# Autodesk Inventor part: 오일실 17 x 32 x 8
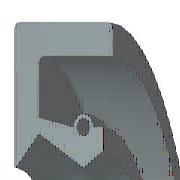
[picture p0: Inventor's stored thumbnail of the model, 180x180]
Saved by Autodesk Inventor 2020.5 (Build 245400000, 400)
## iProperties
Created: 2012-02
Part Number: 오일실 17 x 32 x 8
Material: 고무
Description: 오일-실
Document SubType Name: Modeling
Standard: KS B 2804
Designer: mduedu
Standards Organization: KS
Language: ko-KR
Size Designation: D - 17 32 8
Categories: <MemberInstance><Categories><Category DisplayName="샤프트 부품" InternalName="7f7aeb1f-a693-4053-b835-cee3144e0d98" Mnemonic="SHFT"><Category DisplayName="실링" Intern
Density: 0.93 g/cm^3
Appearance: 고무 - 검은색 - 버전 1.1
IsCustomPart: 1
Author: mduedu
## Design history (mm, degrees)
revolve "본체" stored, may be unused: angle "d17" = 90 deg
revolve "스프링1" stored, may be unused: angle "d18" = 90 deg
body "Solid1"
sketch "스케치1"
  geometry: L1 (0, 16)-(8, 16); L2 (8, 14.25)-(1.75, 14.25); L3 (1.75, 10.25)-(4.9, 8.5); L4 (4.9, 8.5)-(0, 8.5); L5 (0, 0)-(9.586, 0) reference; L6 (4.9, 8.5)-(6.3, 9.375); L7 (0, 18)-(0, -3) reference; L8 (-1.941, 0)-(11.507, 0) reference; L9 (4.2, 10.6)-(1.75, 11.21); L10 (1.75, 11.21)-(1.75, 14.25); L11 (0, 16)-(0, 8.588); L12 (4.9, 8.5)-(0, 8.5); L13 (1.75, 10.25)-(0.152, 8.528); L14 (8, 16)-(8, 14.25); L15 (5.6, 10.6)-(6.3, 10.6); L16 (6.3, 10.6)-(6.3, 9.375); C1 r 0.455 at (4.9, 10.6); A1 r 0.7 centre (4.9, 10.6) between (5.6, 10.6) and (4.2, 10.6); A2 r 0.088 centre (0.088, 8.588) between (0, 8.588) and (0.152, 8.528); 1 further point
  constraints: 28 end point, 5 horizontal alignment, 5 point on line, 4 point on circle, 4 vertical alignment, 3 centre point, 3 tangent, 2 collinear, 2 horizontal, 2 perpendicular, 1 coincident, 1 parallel
  dimensions: "d0" = 32 diameter of L1 L5 (= SD2); "d1" = 1.75 distance of L1.end L2.start (= SD); "d2" = 0.91 diameter of C1 (= SPDI); "d3" = 1.4 diameter of A1 (= SPDA); "d4" = 17 diameter of L3.end L5 (= NND); "d5" = 20.5 diameter of L3.start L5 (= TKDM); "d7" = 22.42 diameter of L9.end L5 (= TKDM + 0.24 x SWDT); "d8" = 1.75 distance between parallel lines of L11 L10 (= SD); "d9" = 4.9 distance from line of L11 C1.centre (= SPDST); "d10" = 21.2 diameter of C1.centre L5 (= HLDM); "d11" = 0.0875 radius of A2 (= 0.25 x LAB); "d12" = 6.3 distance between parallel lines of L11 L16 (= SDI); "d13" = 18.75 diameter of L6.end L5 (= ABDM); "d14" = 8 distance from line of L11 L1.end (= SWDT)
fillet "모깎기1" dims "d6" = 0.3 (= RR)
other parameters: "SD2" = 32 [user parameter; used in 1 equation term], "SWDT" = 8 [user parameter; used in 2 equation terms], "RR" = 0.3 [user parameter; used in 1 equation term], "SD" = 1.75 [user parameter; used in 2 equation terms], "NND" = 17 [user parameter; used in 1 equation term], "SPDA" = 1.4 [user parameter; used in 1 equation term], "SPDI" = 0.91 [user parameter; used in 1 equation term], "TKDM" = 20.5 [user parameter; used in 2 equation terms], "HLDM" = 21.2 [user parameter; used in 1 equation term], "ABDM" = 18.75 [user parameter; used in 1 equation term], "SDI" = 6.3 [user parameter; used in 1 equation term], "SPDST" = 4.9 [user parameter; used in 1 equation term], "LAB" = 0.35 [user parameter; used in 1 equation term], "d15" = 0, "d16" = 0, "d19" = 0
